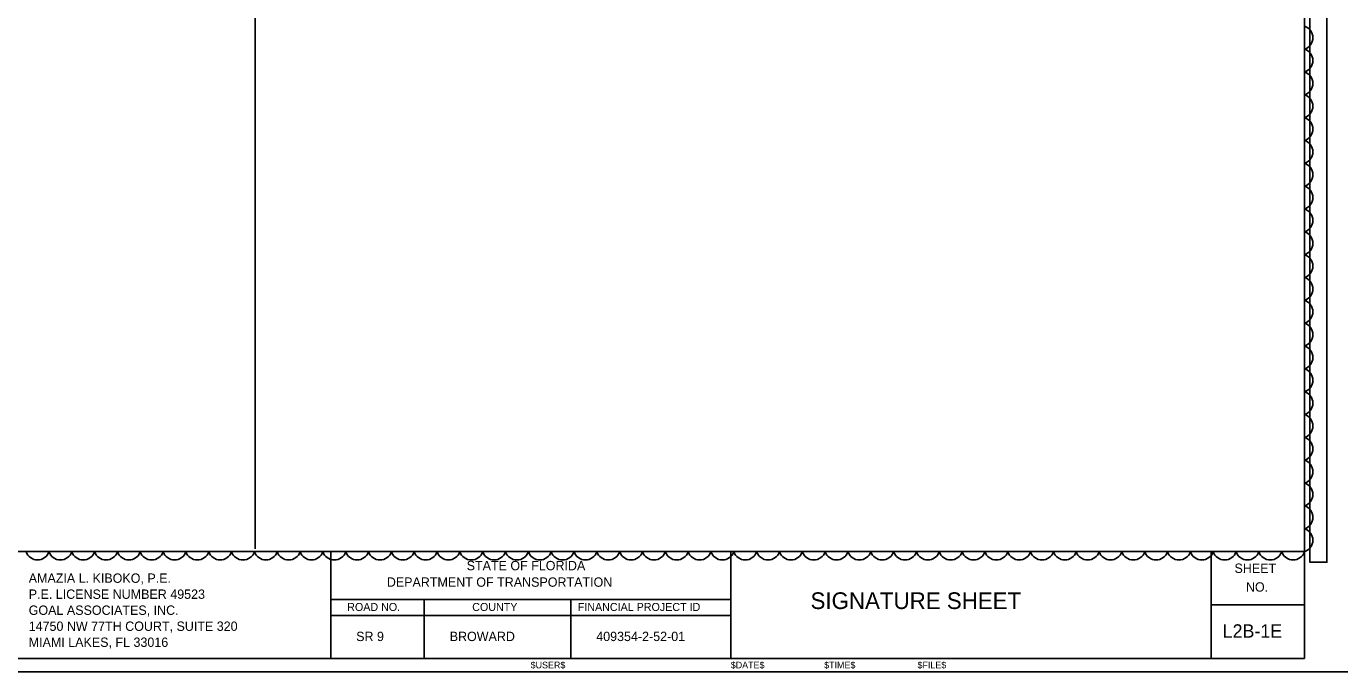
# Model space of a CAD drawing. Extents: x -816.9 to -790.1, y -2199.5 to -2188.9.
# Drawn here: x -804.97 to -795.12, y -2199.5 to -2194.66 of the extents above; entities that cross this region are included whole.
import ezdxf

# ---------------------------------------------------------------- set-up
doc = ezdxf.new("R2010")
doc.units = 0
for name, color, linetype in [('Cloud_dp', 7, 'Continuous'), ('PlotBorder_dp', 7, 'Continuous'), ('ScratchEle_dp', 7, 'Continuous'), ('SheetBorder_dp', 7, 'Continuous'), ('SheetLines_dp', 7, 'Continuous'), ('TextMinor', 7, 'Continuous'), ('TextMisc', 7, 'Continuous'), ('TextShtNo', 7, 'Continuous'), ('TextTitle', 7, 'Continuous')]:
    doc.layers.add(name, color=color, linetype=linetype)

msp = doc.modelspace()

# ---------------------------------------------------------------- linework, layer by layer
at = {"layer": 'Cloud_dp'}
for centre, start, end in [((-795.4127, -2194.7504), 287.5, 72.5), ((-795.4127, -2194.9215), 287.5, 72.5), ((-795.4127, -2195.0926), 287.5, 72.5), ((-795.4127, -2195.2638), 287.5, 72.5), ((-795.4127, -2195.4349), 287.5, 72.5), ((-795.4127, -2195.606), 287.5, 72.5), ((-795.4127, -2195.7771), 287.5, 72.5), ((-795.4127, -2195.9482), 287.5, 72.5), ((-795.4127, -2196.1194), 287.5, 72.5), ((-795.4127, -2196.2905), 287.5, 72.5), ((-795.4127, -2196.4616), 287.5, 72.5), ((-795.4127, -2196.6327), 287.5, 72.5), ((-795.4127, -2196.8039), 287.5, 72.5), ((-795.4127, -2196.975), 287.5, 72.5), ((-795.4127, -2197.1461), 287.5, 72.5), ((-795.4127, -2197.3172), 287.5, 72.5), ((-795.4127, -2197.4883), 287.5, 72.5), ((-795.4127, -2197.6595), 287.5, 72.5), ((-795.4127, -2197.8306), 287.5, 72.5), ((-795.4127, -2198.0017), 287.5, 72.5), ((-795.4127, -2198.1728), 287.5, 72.5), ((-795.4127, -2198.344), 287.5, 72.5), ((-795.4127, -2198.5151), 287.5, 72.5), ((-804.8831, -2198.5737), 197.5, 342.5), ((-804.7119, -2198.5737), 197.5, 342.5), ((-804.5408, -2198.5737), 197.5, 342.5), ((-804.3697, -2198.5737), 197.5, 342.5), ((-804.1986, -2198.5737), 197.5, 342.5), ((-804.0275, -2198.5737), 197.5, 342.5), ((-803.8563, -2198.5737), 197.5, 342.5), ((-803.6852, -2198.5737), 197.5, 342.5), ((-803.5141, -2198.5737), 197.5, 342.5), ((-803.343, -2198.5737), 197.5, 342.5), ((-803.1718, -2198.5737), 197.5, 342.5), ((-803.0007, -2198.5737), 197.5, 342.5), ((-802.8296, -2198.5737), 197.5, 342.5), ((-802.6585, -2198.5737), 197.5, 342.5), ((-802.4874, -2198.5737), 197.5, 342.5), ((-802.3162, -2198.5737), 197.5, 342.5), ((-802.1451, -2198.5737), 197.5, 342.5), ((-801.974, -2198.5737), 197.5, 342.5), ((-801.8029, -2198.5737), 197.5, 342.5), ((-801.6317, -2198.5737), 197.5, 342.5), ((-801.4606, -2198.5737), 197.5, 342.5), ((-801.2895, -2198.5737), 197.5, 342.5), ((-801.1184, -2198.5737), 197.5, 342.5), ((-800.9472, -2198.5737), 197.5, 342.5), ((-800.7761, -2198.5737), 197.5, 342.5), ((-800.605, -2198.5737), 197.5, 342.5), ((-800.4339, -2198.5737), 197.5, 342.5), ((-800.2628, -2198.5737), 197.5, 342.5), ((-800.0916, -2198.5737), 197.5, 342.5), ((-799.9205, -2198.5737), 197.5, 342.5), ((-799.7494, -2198.5737), 197.5, 342.5), ((-799.5783, -2198.5737), 197.5, 342.5), ((-799.4071, -2198.5737), 197.5, 342.5), ((-799.236, -2198.5737), 197.5, 342.5), ((-799.0649, -2198.5737), 197.5, 342.5), ((-798.8938, -2198.5737), 197.5, 342.5), ((-798.7227, -2198.5737), 197.5, 342.5), ((-798.5515, -2198.5737), 197.5, 342.5), ((-798.3804, -2198.5737), 197.5, 342.5), ((-798.2093, -2198.5737), 197.5, 342.5), ((-798.0382, -2198.5737), 197.5, 342.5), ((-797.867, -2198.5737), 197.5, 342.5), ((-797.6959, -2198.5737), 197.5, 342.5), ((-797.5248, -2198.5737), 197.5, 342.5), ((-797.3537, -2198.5737), 197.5, 342.5), ((-797.1826, -2198.5737), 197.5, 342.5), ((-797.0114, -2198.5737), 197.5, 342.5), ((-796.8403, -2198.5737), 197.5, 342.5), ((-796.6692, -2198.5737), 197.5, 342.5), ((-796.4981, -2198.5737), 197.5, 342.5), ((-796.3269, -2198.5737), 197.5, 342.5), ((-796.1558, -2198.5737), 197.5, 342.5), ((-795.9847, -2198.5737), 197.5, 342.5), ((-795.8136, -2198.5737), 197.5, 342.5), ((-795.6425, -2198.5737), 197.5, 342.5), ((-795.4713, -2198.5737), 197.5, 342.5)]:
    msp.add_arc(centre, 0.0897, start, end, dxfattribs=at)
at = {"layer": 'PlotBorder_dp'}
msp.add_lwpolyline([(-811.3358, -2199.5006), (-794.8358, -2199.5006), (-794.8358, -2188.9006), (-811.3358, -2188.9006)], close=True, dxfattribs=at)
at = {"layer": 'ScratchEle_dp'}
msp.add_lwpolyline([(-795.3456, -2191.8382), (-795.218, -2191.8382), (-795.218, -2198.6801), (-795.3456, -2198.6801)], close=True, dxfattribs=at)
at = {"layer": 'SheetBorder_dp'}
for p, q in [((-803.2512, -2198.5798), (-803.2512, -2188.9798)), ((-795.3858, -2189.0006), (-795.3858, -2199.4006)), ((-810.7858, -2198.6006), (-795.3858, -2198.6006)), ((-810.7858, -2199.4006), (-795.3858, -2199.4006))]:
    msp.add_line(p, q, dxfattribs=at)
at = {"layer": 'SheetLines_dp'}
for p, q in [((-802.6858, -2198.6006), (-802.6858, -2199.4006)), ((-799.6858, -2199.4006), (-799.6858, -2198.6006)), ((-796.0858, -2199.4006), (-796.0858, -2198.6006)), ((-802.6858, -2198.9606), (-799.6858, -2198.9606)), ((-801.9858, -2198.9606), (-801.9858, -2199.4006)), ((-800.8858, -2198.9606), (-800.8858, -2199.4006)), ((-796.0858, -2199.0006), (-795.3858, -2199.0006)), ((-802.6858, -2199.0806), (-799.6858, -2199.0806))]:
    msp.add_line(p, q, dxfattribs=at)

# ---------------------------------------------------------------- texts
at = {"layer": 'TextMinor'}
msp.add_text('$USER$', height=0.05, dxfattribs=at).set_placement((-801.1868, -2199.4756))
for s, p in [('$DATE$', (-799.6868, -2199.4756)), ('$TIME$', (-798.9868, -2199.4756)), ('$FILE$', (-798.2868, -2199.4756))]:
    msp.add_text(s, height=0.05, rotation=360, dxfattribs=at).set_placement(p)
at = {"layer": 'TextMisc'}
for s, height, p in [('STATE OF FLORIDA', 0.07, (-801.6664, -2198.7405)), ('DEPARTMENT OF TRANSPORTATION', 0.07, (-802.265, -2198.8641)), ('       SIGNATURE SHEET         ', 0.125, (-799.414, -2199.0309)), ('ROAD NO.', 0.06, (-802.5619, -2199.0455)), ('COUNTY', 0.06, (-801.6248, -2199.0455)), ('FINANCIAL PROJECT ID', 0.06, (-800.8335, -2199.0455)), (' SR 9  ', 0.07, (-802.5207, -2199.271)), ('  BROWARD   ', 0.07, (-801.8455, -2199.271)), ('409354-2-52-01', 0.07, (-800.6951, -2199.271))]:
    msp.add_text(s, height=height, dxfattribs=at).set_placement(p)
for s, p in [('SHEET', (-795.911, -2198.7601)), ('NO.', (-795.8253, -2198.9003))]:
    msp.add_text(s, height=0.07, rotation=359.86066, dxfattribs=at).set_placement(p)
at = {"layer": 'TextShtNo'}
msp.add_text('L2B-1E', height=0.1, dxfattribs=at).set_placement((-795.9993, -2199.2455))
at = {"layer": 'TextTitle'}
for s, p in [('AMAZIA L. KIBOKO, P.E.', (-804.9493, -2198.8346)), ('P.E. LICENSE NUMBER 49523', (-804.9493, -2198.9546)), ('GOAL ASSOCIATES, INC.', (-804.9493, -2199.0746)), ('14750 NW 77TH COURT, SUITE 320', (-804.9493, -2199.1946)), ('MIAMI LAKES, FL 33016', (-804.9493, -2199.3146))]:
    msp.add_text(s, height=0.07, dxfattribs=at).set_placement(p)

doc.saveas('drawing.dxf')
